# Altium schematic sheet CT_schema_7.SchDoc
size 366 x 336 mm
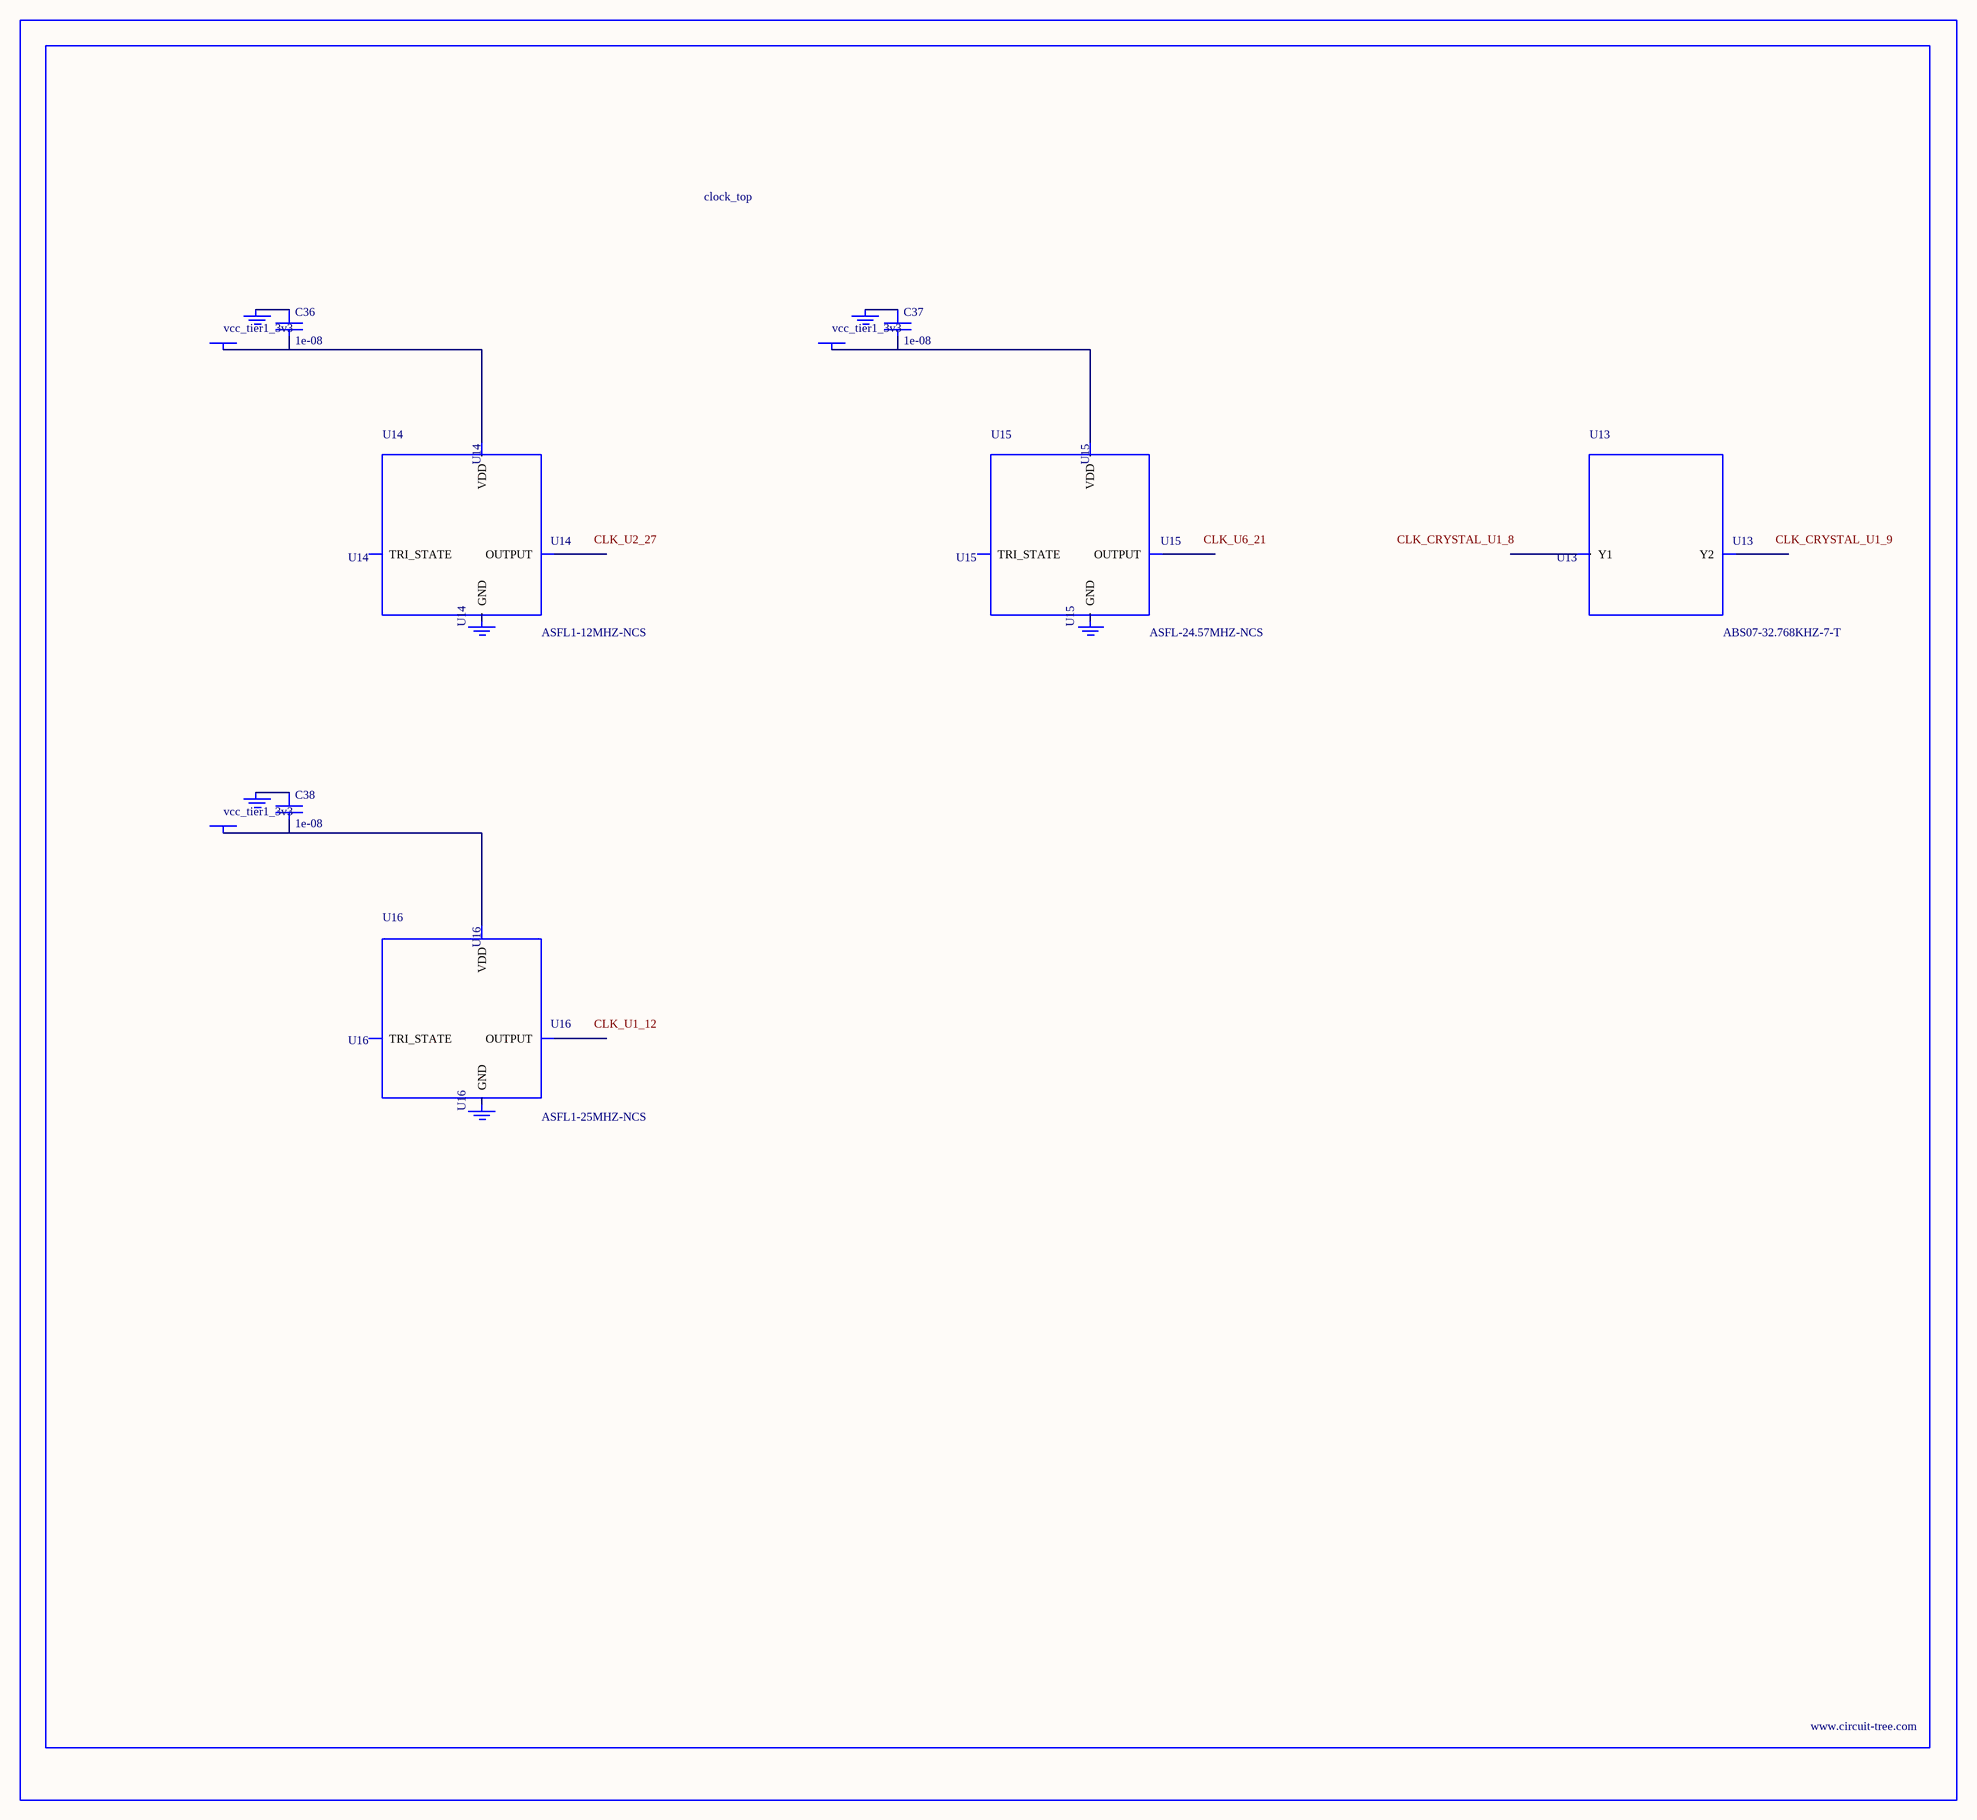
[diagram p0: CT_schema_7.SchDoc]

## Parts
BORDER6  (no value)
C36  1e-08  [C0402]
C37  1e-08  [C0402]
C38  1e-08  [C0402]
GND_INSTANCE_6_0  (no value)
GND_INSTANCE_6_1  (no value)
GND_INSTANCE_6_2  (no value)
GND_INSTANCE_6_3  (no value)
GND_INSTANCE_6_4  (no value)
GND_INSTANCE_6_5  (no value)
POWER_INSTANCE_6_0  vcc_tier1_3v3
POWER_INSTANCE_6_1  vcc_tier1_3v3
POWER_INSTANCE_6_2  vcc_tier1_3v3
U13  ABS07-32.768KHZ-7-T  [ABS07-32.768KHZ-7-T]
U14  ASFL1-12MHZ-NCS  [ASFL1]
U15  ASFL-24.57MHZ-NCS  [ASFL1]
U16  ASFL1-25MHZ-NCS  [ASFL1]

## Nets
NetC36_1: C36.1 GND_INSTANCE_6_0.0(GND)
NetC36_2: C36.2 POWER_INSTANCE_6_0.0(PWR) U14.4(VDD)
NetC37_1: C37.1 GND_INSTANCE_6_2.0(GND)
NetC37_2: C37.2 POWER_INSTANCE_6_1.0(PWR) U15.4(VDD)
NetC38_1: C38.1 GND_INSTANCE_6_4.0(GND)
NetC38_2: C38.2 POWER_INSTANCE_6_2.0(PWR) U16.4(VDD)

Not connected (* = marked no-connect by the designer): GND_INSTANCE_6_1 0(GND); GND_INSTANCE_6_3 0(GND); GND_INSTANCE_6_5 0(GND); U13 1(Y1) 2(Y2); U14 1(TRI_STATE) 2(GND) 3(OUTPUT); U15 1(TRI_STATE) 2(GND) 3(OUTPUT); U16 1(TRI_STATE) 2(GND) 3(OUTPUT)

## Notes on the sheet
- Labels drawn without touching a wire or pin: CLK_CRYSTAL_U1_8, CLK_CRYSTAL_U1_9, CLK_U1_12, CLK_U2_27, CLK_U6_21

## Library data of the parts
BORDER6 = BORDER_PAGE6
C36-C38 = C0402C103K3RAC
GND_INSTANCE_6_0-GND_INSTANCE_6_5 = GND
POWER_INSTANCE_6_0-POWER_INSTANCE_6_2 = PWR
